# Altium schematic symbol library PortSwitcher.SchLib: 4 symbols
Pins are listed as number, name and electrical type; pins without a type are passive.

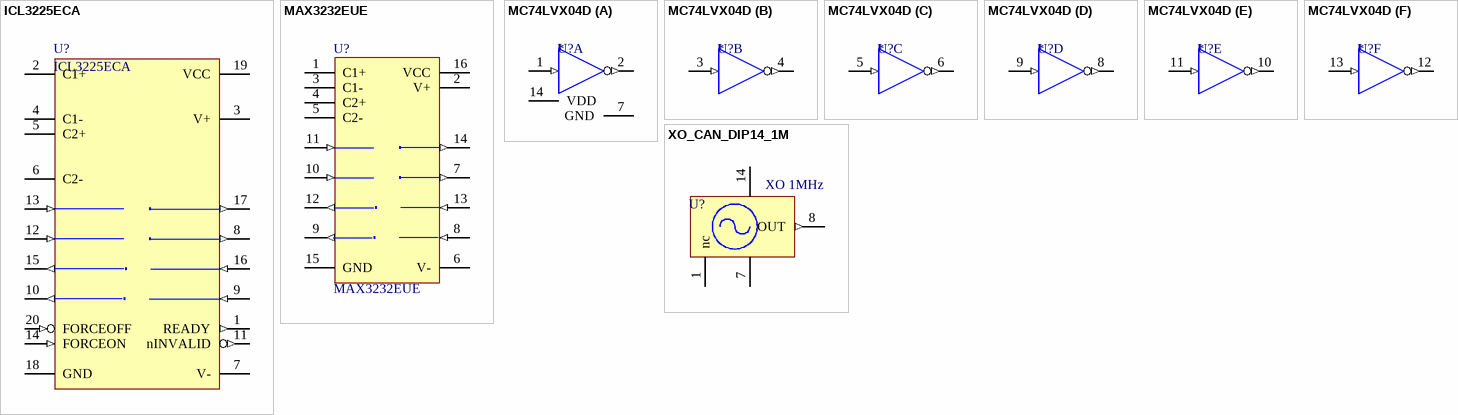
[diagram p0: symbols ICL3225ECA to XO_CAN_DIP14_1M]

## ICL3225ECA
designator U?
3.0V TO 5.5V, Low-Power, up to 1Mbps, True RS-232 Transceiver Using Four 0.1µF External Capacitor
footprint SSO-G20/P.65
pins: 1 READY (out), 2 C1+, 3 V+ (power), 4 C1-, 5 C2+, 6 C2-, 7 V- (power), 8 T2OUT (out), 9 R2IN (in), 10 R2OUT (out), 11 nINVALID (out), 12 T2IN (in), 13 T1IN (in), 14 FORCEON (in), 15 R1OUT (out), 16 R1IN (in), 17 T1OUT (out), 18 GND (power), 19 VCC (power), 20 FORCEOFF (in)

## MAX3232EUE
designator U?
3.0V TO 5.5V, Low-Power, up to 1Mbps, True RS-232 Transceiver Using Four 0.1µF External Capacitor; Manufacturer: Maxim,ST; Package Information: Latest Revision: 21-0066 C; Class I: Communication
footprint SO-G16
pins: 1 C1+, 2 V+ (power), 3 C1-, 4 C2+, 5 C2-, 6 V- (power), 7 T2OUT (out), 8 R2IN (in), 9 R2OUT (out), 10 T2IN (in), 11 T1IN (in), 12 R1OUT (out), 13 R1IN (in), 14 T1OUT (out), 15 GND (power), 16 VCC (power)

## MC74LVX04D
designator U?
Hex Inverter with 5V-Tolerant Inputs; Manufacturer: ON Semiconductor; Code - JEDEC: MS-012-AB; Code - IPC: SO14
footprint 751A-03 (Small Outline; 14 Leads; Body Width 3.9 mm; Pitch 1.27 mm)
part A pins: 1 IN (in), 2 ~{OUT} (out), 7 GND (power), 14 VDD (power)
part B pins: 3 IN (in), 4 ~{OUT} (out)
part C pins: 5 IN (in), 6 ~{OUT} (out)
part D pins: 8 ~{OUT} (out), 9 IN (in)
part E pins: 10 ~{OUT} (out), 11 IN (in)
part F pins: 12 ~{OUT} (out), 13 IN (in)

## XO_CAN_DIP14_1M
designator U?, comment XO 1MHz
IC, Oscillator, Canned, CMOS o/p, General Purpose, No Enable/Disable, 1MHz; Text Field1: TBA
footprint Model Name (Footprint not found)
pins: 1 nc, 7 GND (power), 8 OUT (out), 14 VCC (power)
